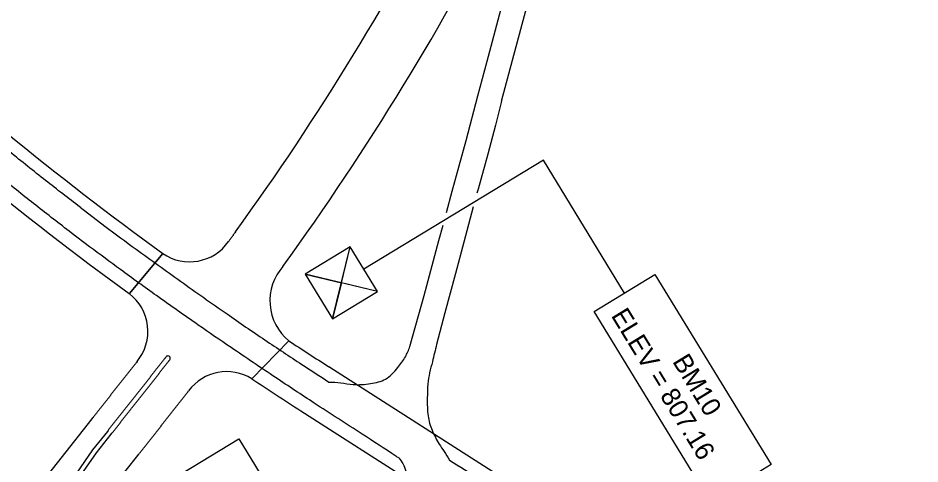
# Model space of a CAD drawing. Extents: x 1771071 to 1790027, y 804210 to 823391.
# Drawn here: x 1782402 to 1783163, y 814217 to 814593 of the extents above; entities that cross this region are included whole.
import ezdxf

# ---------------------------------------------------------------- set-up
doc = ezdxf.new("R2010")
doc.units = 0
for name, color, linetype in [('Default', 7, 'Continuous'), ('Exist Roads EOP', 7, 'Continuous'), ('Old_Level_57', 7, 'Continuous'), ('Prop Dimension Text', 7, 'Continuous'), ('Proposed Right of Way Monument PSD Text', 7, 'Continuous'), ('Scratch_Level_1', 7, 'Continuous'), ('Scratch_Level_8', 7, 'Continuous')]:
    doc.layers.add(name, color=color, linetype=linetype)

msp = doc.modelspace()

# ---------------------------------------------------------------- linework, layer by layer
at = {"layer": 'Default'}
msp.add_lwpolyline([(1782914.26, 814360.69), (1782845.7, 814472.9), (1782694.13, 814380.96)], dxfattribs=at)
for points in [[(1782939.86, 814376.33), (1783037.78, 814216.07), (1782986.58, 814184.78), (1782888.66, 814345.05)], [(1782588.69, 814237.9), (1782699.11, 814057.19), (1782626.99, 814013.12), (1782516.58, 814193.83)]]:
    msp.add_lwpolyline(points, close=True, dxfattribs=at)
at = {"layer": 'Exist Roads EOP'}
for points in [[(1782810.5, 814522.45), (1782819.71, 814557.13), (1782833.63, 814609.67), (1782845.19, 814652.34), (1782853.11, 814682.7), (1782866.83, 814733.67), (1782880.33, 814784.04), (1782896.83, 814847.05), (1782904.69, 814876.34), (1782917.48, 814926.43), (1782930.77, 814976.43), (1782943.98, 815026.78), (1782949.05, 815045.92), (1782955.94, 815070.93), (1782968.77, 815118.62), (1782976.32, 815145.42), (1782981.66, 815163.9), (1782994.39, 815213.76), (1783001.18, 815239.78), (1783009.61, 815271.62)], [(1782798.27, 814556.34), (1782809.82, 814599.63), (1782821.24, 814641.98), (1782833.33, 814687.58), (1782844.77, 814730.36), (1782855.02, 814768.66), (1782860.01, 814788.32), (1782866.57, 814813.78), (1782876.56, 814850.36), (1782887.82, 814892.28), (1782899.33, 814935.44), (1782909.53, 814975.79), (1782921.25, 815019.23), (1782932.71, 815062.01), (1782944.15, 815104.21), (1782955.09, 815145.17), (1782966.82, 815189.08), (1782971.17, 815207.42), (1782981.42, 815245.29), (1782983.08, 815250.42)], [(1782763.97, 814428.7), (1782768.85, 814446.71), (1782780.46, 814489.35), (1782790.34, 814526.96), (1782798.27, 814556.34)], [(1782810.5, 814522.45), (1782805.42, 814502.23), (1782798.82, 814477.74), (1782790.59, 814448.3), (1782789.65, 814444.83)], [(1782786.58, 814433.49), (1782778.49, 814403.65), (1782771.5, 814377.24), (1782762.64, 814343.92), (1782755.65, 814317.36)], [(1782733.16, 814315.62), (1782745.18, 814358.58), (1782757.57, 814405.12), (1782761.06, 814418)]]:
    msp.add_lwpolyline(points, dxfattribs=at)
for points in [[(1782454.8, 814433.05), (1782425.79, 814455.52), (1782395.47, 814479.87), (1782368.44, 814502.06), (1782336.7, 814528.74), (1782306.5, 814555), (1782272.52, 814585.37), (1782237.96, 814617.26), (1782203.42, 814650.14), (1782169.77, 814683.38), (1782135.62, 814718.19), (1782114.92, 814739.97), (1782090.36, 814766.45), (1782056.11, 814804.23), (1782024.57, 814840.15), (1781996.1, 814874.23), (1781962.65, 814915.16), (1781930.52, 814956.23), (1781901.27, 814994.73), (1781879.88, 815023.5), (1781865.55, 815043.2)], [(1782447.39, 814411.49), (1782417.41, 814434.76), (1782388.46, 814457.81), (1782364.95, 814476.92), (1782332.84, 814503.63), (1782317.89, 814516.39), (1782288.73, 814541.74), (1782259.15, 814568.04), (1782231.71, 814593.59), (1782203.19, 814620.46), (1782173.93, 814648.95), (1782145.34, 814677.22), (1782115.25, 814707.98), (1782082.01, 814743.51), (1782053.72, 814774.62), (1782020.97, 814811.58), (1781993.17, 814843.95), (1781966.57, 814876.13), (1781940.26, 814908.56), (1781913.84, 814942.34), (1781892.83, 814970.15), (1781866.04, 815005.9), (1781848.36, 815030.23)], [(1781123.7, 814794.56), (1781151.95, 814749.7), (1781175.35, 814711.94), (1781204.02, 814667.22), (1781230.05, 814626.42), (1781255.51, 814585.11), (1781282.93, 814541.39), (1781309.04, 814500.81), (1781338.07, 814453.82), (1781362.44, 814415.66), (1781389.1, 814373.22), (1781417.2, 814328.4), (1781443.82, 814286), (1781469.22, 814245.27), (1781496.33, 814201.88), (1781523.28, 814159.28), (1781551.49, 814114.9), (1781575, 814076.8), (1781602.27, 814034.47), (1781628.68, 813992.42), (1781657.71, 813946.44), (1781682.97, 813906.24), (1781710.54, 813862.11), (1781734.73, 813823.58), (1781763.09, 813779.24), (1781788.41, 813738.38), (1781814.81, 813696.35), (1781842.37, 813653.36), (1781868.91, 813610.68), (1781895.83, 813568.71), (1781924.39, 813523.58), (1781950.61, 813481.8), (1781976.68, 813442.67), (1782004.37, 813401.37), (1782031.99, 813360.12), (1782060.77, 813317.53), (1782089.19, 813276.64), (1782119.2, 813233.31), (1782146.2, 813195.67), (1782175.13, 813155.14), (1782204.07, 813115.4), (1782233.24, 813075.72), (1782263.79, 813034.43), (1782294.03, 812994.29), (1782325.04, 812953.86), (1782354.41, 812916.21), (1782385, 812877.38), (1782417.21, 812837.26), (1782449.43, 812797.65), (1782479.54, 812761.76), (1782513.17, 812720.66), (1782543.05, 812684.98), (1782576.35, 812645.89), (1782608.48, 812608.74), (1782640.69, 812571.37), (1782677.39, 812530.96), (1782710.34, 812494.65), (1782741.2, 812460.83), (1782775.54, 812424.09), (1782810.15, 812387.02), (1782844.36, 812350.73), (1782880.69, 812313.19), (1782914.85, 812277.64), (1782949.87, 812242.16), (1782985.13, 812206.92), (1783022.44, 812170.42), (1783054.86, 812138.57), (1783094.75, 812100.54), (1783130.02, 812066.91), (1783162.74, 812036.24), (1783200.85, 812001.49), (1783239.6, 811965.96), (1783275.52, 811933.35), (1783312.46, 811900.79)], [(1782664.68, 814285.69), (1782674.84, 814285.07), (1782685.21, 814283.59), (1782699.97, 814284.44), (1782712.52, 814288.15), (1782722.95, 814298), (1782729.29, 814306.99), (1782733.16, 814315.62)], [(1782755.65, 814317.36), (1782752.06, 814302.79), (1782748.2, 814284.21), (1782747.8, 814272.16), (1782748.44, 814257.13), (1782751.78, 814245), (1782757.87, 814233.38), (1782761.88, 814227.14), (1782766.5, 814219.88)], [(1782723.67, 814221.68), (1782727.13, 814216.98), (1782729.81, 814210.47), (1782732.01, 814203.23), (1782733.27, 814197.25), (1782734.23, 814187.61)]]:
    msp.add_spline(points, degree=3, dxfattribs=at)
at = {"layer": 'Old_Level_57'}
for p, q in [((1782667.92, 814339.04), (1782682.6, 814399.83)), ((1782705.65, 814362.09), (1782644.86, 814376.77))]:
    msp.add_line(p, q, dxfattribs=at)
msp.add_lwpolyline([(1782682.6, 814399.83), (1782644.86, 814376.77), (1782667.92, 814339.04), (1782705.65, 814362.09)], close=True, dxfattribs=at)
for points in [[(1782675.26, 814369.43), (1782682.6, 814399.83), (1782644.86, 814376.77), (1782675.26, 814369.43)], [(1782675.26, 814369.43), (1782667.92, 814339.04), (1782705.65, 814362.09), (1782675.26, 814369.43)]]:
    msp.add_lwpolyline(points, dxfattribs=at)
at = {"layer": 'Prop Dimension Text'}
for p, q in [((1782530.59, 814306.82), (1782529.6, 814307.59)), ((1782477.83, 814244.1), (1782465.41, 814228.41)), ((1782468.56, 814225.95), (1782480.97, 814241.62)), ((1782465.41, 814228.41), (1782350.67, 814064.15)), ((1782353.82, 814061.69), (1782468.56, 814225.95))]:
    msp.add_line(p, q, dxfattribs=at)
msp.add_lwpolyline([(1782527.36, 814306.96), (1782527.36, 814306.96)], dxfattribs=at)
for start, end in [(70.46317, 141.44737), (321.44737, 33.62467)]:
    msp.add_arc((1782528.93, 814305.71), 2, start, end, dxfattribs=at)
for points in [[(1782527.36, 814306.96), (1782527.01, 814306.51), (1782526.66, 814306.06), (1782526.31, 814305.61), (1782525.76, 814304.91), (1782525.21, 814304.2), (1782524.65, 814303.49), (1782524.1, 814302.78), (1782523.54, 814302.07), (1782522.99, 814301.36), (1782522.44, 814300.65), (1782521.88, 814299.94), (1782521.33, 814299.24), (1782520.77, 814298.53), (1782520.22, 814297.82), (1782519.66, 814297.11), (1782519.11, 814296.4), (1782518.55, 814295.69), (1782518, 814294.99), (1782517.44, 814294.28), (1782516.88, 814293.57), (1782516.33, 814292.86), (1782515.77, 814292.15), (1782515.22, 814291.45), (1782514.66, 814290.74), (1782514.11, 814290.03), (1782513.55, 814289.32), (1782512.99, 814288.62), (1782512.44, 814287.91), (1782511.88, 814287.2), (1782511.32, 814286.49), (1782510.77, 814285.79), (1782510.21, 814285.08), (1782509.65, 814284.37), (1782509.1, 814283.66), (1782508.54, 814282.96), (1782507.98, 814282.25), (1782507.43, 814281.54), (1782506.87, 814280.84), (1782506.31, 814280.13), (1782505.76, 814279.42), (1782505.2, 814278.71), (1782504.64, 814278.01), (1782504.08, 814277.3), (1782503.53, 814276.59), (1782502.97, 814275.89), (1782502.41, 814275.18), (1782501.85, 814274.47), (1782501.3, 814273.77), (1782500.74, 814273.06), (1782500.18, 814272.35), (1782499.62, 814271.65), (1782499.06, 814270.94), (1782498.51, 814270.23), (1782497.95, 814269.53), (1782497.39, 814268.82), (1782496.83, 814268.11), (1782496.27, 814267.41), (1782495.71, 814266.7), (1782495.16, 814265.99), (1782494.6, 814265.29), (1782494.04, 814264.58), (1782493.48, 814263.88), (1782492.92, 814263.17), (1782492.36, 814262.46), (1782491.81, 814261.76), (1782491.25, 814261.05), (1782490.69, 814260.34), (1782490.13, 814259.64), (1782489.57, 814258.93), (1782489.01, 814258.22), (1782488.45, 814257.52), (1782487.89, 814256.81), (1782487.34, 814256.11), (1782486.78, 814255.4), (1782486.22, 814254.69), (1782485.66, 814253.99), (1782485.1, 814253.28), (1782484.54, 814252.57), (1782483.98, 814251.87), (1782483.42, 814251.16), (1782482.86, 814250.46), (1782482.3, 814249.75), (1782481.75, 814249.04), (1782481.19, 814248.34), (1782480.63, 814247.63), (1782480.07, 814246.92), (1782479.51, 814246.22), (1782478.95, 814245.51), (1782478.39, 814244.81), (1782477.83, 814244.1)], [(1782480.97, 814241.62), (1782481.53, 814242.32), (1782482.09, 814243.03), (1782482.64, 814243.73), (1782483.2, 814244.44), (1782483.76, 814245.15), (1782484.32, 814245.85), (1782484.88, 814246.56), (1782485.44, 814247.27), (1782486, 814247.97), (1782486.56, 814248.68), (1782487.12, 814249.39), (1782487.68, 814250.09), (1782488.24, 814250.8), (1782488.8, 814251.5), (1782489.35, 814252.21), (1782489.91, 814252.92), (1782490.47, 814253.62), (1782491.03, 814254.33), (1782491.59, 814255.04), (1782492.15, 814255.74), (1782492.71, 814256.45), (1782493.27, 814257.16), (1782493.83, 814257.86), (1782494.38, 814258.57), (1782494.94, 814259.27), (1782495.5, 814259.98), (1782496.06, 814260.69), (1782496.62, 814261.39), (1782497.18, 814262.1), (1782497.74, 814262.81), (1782498.29, 814263.51), (1782498.85, 814264.22), (1782499.41, 814264.93), (1782499.97, 814265.63), (1782500.53, 814266.34), (1782501.09, 814267.05), (1782501.64, 814267.75), (1782502.2, 814268.46), (1782502.76, 814269.17), (1782503.32, 814269.88), (1782503.88, 814270.58), (1782504.44, 814271.29), (1782504.99, 814272), (1782505.55, 814272.7), (1782506.11, 814273.41), (1782506.67, 814274.12), (1782507.22, 814274.82), (1782507.78, 814275.53), (1782508.34, 814276.24), (1782508.9, 814276.95), (1782509.45, 814277.65), (1782510.01, 814278.36), (1782510.57, 814279.07), (1782511.13, 814279.78), (1782511.68, 814280.48), (1782512.24, 814281.19), (1782512.8, 814281.9), (1782513.35, 814282.61), (1782513.91, 814283.31), (1782514.47, 814284.02), (1782515.02, 814284.73), (1782515.58, 814285.44), (1782516.14, 814286.14), (1782516.69, 814286.85), (1782517.25, 814287.56), (1782517.81, 814288.27), (1782518.36, 814288.98), (1782518.92, 814289.68), (1782519.48, 814290.39), (1782520.03, 814291.1), (1782520.59, 814291.81), (1782521.14, 814292.52), (1782521.7, 814293.23), (1782522.25, 814293.94), (1782522.81, 814294.64), (1782523.36, 814295.35), (1782523.92, 814296.06), (1782524.48, 814296.77), (1782525.03, 814297.48), (1782525.59, 814298.19), (1782526.14, 814298.9), (1782526.69, 814299.61), (1782527.25, 814300.32), (1782527.8, 814301.02), (1782528.36, 814301.73), (1782528.91, 814302.44), (1782529.47, 814303.15), (1782529.81, 814303.59), (1782530.15, 814304.03), (1782530.49, 814304.46)]]:
    msp.add_open_spline(points, degree=3, dxfattribs=at)
at = {"layer": 'Scratch_Level_1'}
for p, q in [((1782454.8, 814433.05), (1782475.72, 814417.11)), ((1782462.86, 814399.8), (1782447.39, 814411.49))]:
    msp.add_line(p, q, dxfattribs=at)
for points in [[(1782475.72, 814417.11), (1782502.13, 814397.66), (1782539.56, 814370.71), (1782578.8, 814343.11), (1782610.76, 814321.2), (1782641.94, 814300.58), (1782664.68, 814285.69)], [(1782723.67, 814221.68), (1782721.33, 814223.19), (1782692.8, 814241.75), (1782652.47, 814267.87), (1782619.8, 814289.45), (1782582.18, 814314.76), (1782554.6, 814333.65), (1782519.33, 814358.55), (1782488.95, 814380.46), (1782462.86, 814399.8)], [(1782766.5, 814219.88), (1782791.69, 814203.81), (1782832.73, 814177.58)]]:
    msp.add_spline(points, degree=3, dxfattribs=at)
at = {"layer": 'Scratch_Level_8'}
for p, q in [((1782496.39, 814360.22), (1782524.58, 814394.12)), ((1782496.39, 814360.22), (1782524.58, 814394.12)), ((1782524.58, 814394.12), (1782496.39, 814360.22)), ((1782630.97, 814320.49), (1782599.81, 814288.35)), ((1782630.97, 814320.49), (1782599.81, 814288.35)), ((1782599.81, 814288.35), (1782630.97, 814320.49)), ((1783161.34, 813981.02), (1782664.74, 814298.57)), ((1782641.03, 814261.5), (1783137.64, 813943.95)), ((1782464.72, 814254.56), (1781921.58, 813568.53)), ((1782274, 813933.92), (1782503.53, 814223.83))]:
    msp.add_line(p, q, dxfattribs=at)
for centre, radius, start, end in [((1784215.15, 816723.25), 2878, 220.79704, 234.02645), ((1784215.15, 816723.25), 2922, 220.79704, 233.96949), ((1780718.84, 815764.32), 2305.25, 324.09033, 332.9908), ((1780718.84, 815764.32), 2354.75, 324.08963, 332.9908), ((1782547.27, 814427.08), 40.01, 235.46267, 325.28496), ((1782658.46, 814354.21), 43.51, 138.18524, 230.81193), ((1782472.08, 814328.44), 40.01, 320.48337, 52.58911), ((1784215.15, 816723.25), 2878, 236.60245, 237.40395), ((1782578.6, 814254.42), 40.01, 57.98892, 143.47609), ((1784215.15, 816723.25), 2922, 236.43927, 237.40395)]:
    msp.add_arc(centre, radius, start, end, dxfattribs=at)
for points in [[(1782585.96, 814412.27), (1782585.44, 814411.55), (1782584.91, 814410.82), (1782584.38, 814410.1), (1782583.86, 814409.38), (1782583.34, 814408.65), (1782582.81, 814407.93), (1782582.29, 814407.21), (1782581.76, 814406.49), (1782581.24, 814405.77), (1782580.88, 814405.28), (1782580.52, 814404.79), (1782580.16, 814404.29)], [(1782502.94, 814302.98), (1782502.47, 814302.37), (1782501.99, 814301.76), (1782501.51, 814301.15), (1782500.95, 814300.44), (1782500.4, 814299.74), (1782499.84, 814299.03), (1782499.29, 814298.32), (1782498.73, 814297.62), (1782498.18, 814296.91), (1782497.62, 814296.2), (1782497.07, 814295.5), (1782496.51, 814294.79), (1782495.95, 814294.09), (1782495.4, 814293.38), (1782494.84, 814292.67), (1782494.29, 814291.97), (1782493.73, 814291.26), (1782493.17, 814290.56), (1782492.62, 814289.85), (1782492.06, 814289.15), (1782491.5, 814288.44), (1782490.95, 814287.73), (1782490.39, 814287.03), (1782489.83, 814286.32), (1782489.28, 814285.62), (1782488.72, 814284.91), (1782488.16, 814284.2), (1782487.61, 814283.5), (1782487.05, 814282.79), (1782486.49, 814282.09), (1782485.94, 814281.38), (1782485.38, 814280.68), (1782484.82, 814279.97), (1782484.26, 814279.26), (1782483.71, 814278.56), (1782483.15, 814277.85), (1782482.59, 814277.15), (1782482.03, 814276.44), (1782481.47, 814275.74), (1782480.92, 814275.03), (1782480.36, 814274.32), (1782479.8, 814273.62), (1782479.24, 814272.91), (1782478.68, 814272.21), (1782478.13, 814271.5), (1782477.57, 814270.8), (1782477.01, 814270.09), (1782476.45, 814269.38), (1782475.89, 814268.68), (1782475.33, 814267.97), (1782474.78, 814267.27), (1782474.22, 814266.56), (1782473.66, 814265.85), (1782473.1, 814265.15), (1782472.54, 814264.44), (1782471.98, 814263.74), (1782471.42, 814263.03), (1782470.87, 814262.32), (1782470.31, 814261.62), (1782469.75, 814260.91), (1782469.19, 814260.21), (1782468.63, 814259.5), (1782468.07, 814258.79), (1782467.51, 814258.09), (1782466.95, 814257.38), (1782466.39, 814256.68), (1782465.83, 814255.97), (1782465.27, 814255.26), (1782464.72, 814254.56)], [(1782503.53, 814223.83), (1782504.08, 814224.54), (1782504.64, 814225.24), (1782505.2, 814225.95), (1782505.76, 814226.66), (1782506.32, 814227.36), (1782506.88, 814228.07), (1782507.44, 814228.78), (1782508, 814229.48), (1782508.56, 814230.19), (1782509.12, 814230.9), (1782509.68, 814231.6), (1782510.24, 814232.31), (1782510.8, 814233.02), (1782511.36, 814233.72), (1782511.92, 814234.43), (1782512.48, 814235.14), (1782513.03, 814235.84), (1782513.59, 814236.55), (1782514.15, 814237.26), (1782514.71, 814237.97), (1782515.27, 814238.67), (1782515.83, 814239.38), (1782516.39, 814240.09), (1782516.95, 814240.79), (1782517.51, 814241.5), (1782518.07, 814242.21), (1782518.63, 814242.92), (1782519.19, 814243.63), (1782519.75, 814244.33), (1782520.31, 814245.04), (1782520.87, 814245.75), (1782521.43, 814246.46), (1782521.99, 814247.16), (1782522.55, 814247.87), (1782523.11, 814248.58), (1782523.66, 814249.29), (1782524.22, 814250), (1782524.78, 814250.7), (1782525.34, 814251.41), (1782525.9, 814252.12), (1782526.46, 814252.83), (1782527.02, 814253.54), (1782527.58, 814254.25), (1782528.14, 814254.96), (1782528.7, 814255.66), (1782529.26, 814256.37), (1782529.82, 814257.08), (1782530.38, 814257.79), (1782530.93, 814258.5), (1782531.49, 814259.21), (1782532.05, 814259.92), (1782532.61, 814260.63), (1782533.17, 814261.34), (1782533.73, 814262.05), (1782534.29, 814262.76), (1782534.85, 814263.47), (1782535.41, 814264.18), (1782535.96, 814264.89), (1782536.52, 814265.6), (1782537.08, 814266.31), (1782537.64, 814267.02), (1782538.2, 814267.73), (1782538.76, 814268.44), (1782539.32, 814269.15), (1782539.87, 814269.86), (1782540.43, 814270.57), (1782540.99, 814271.28), (1782541.55, 814271.99), (1782542.11, 814272.7), (1782542.67, 814273.41), (1782543.22, 814274.12), (1782543.78, 814274.84), (1782544.34, 814275.55), (1782544.9, 814276.26), (1782545.45, 814276.97), (1782545.78, 814277.39), (1782546.11, 814277.81), (1782546.44, 814278.23)]]:
    msp.add_open_spline(points, degree=3, dxfattribs=at)

# ---------------------------------------------------------------- texts
at = {"layer": 'Proposed Right of Way Monument PSD Text'}
for s, p in [('ELEV = 807.16', (1782902.41, 814341.73)), ('BM10', (1782954.15, 814303.07))]:
    msp.add_text(s, height=16, rotation=301.42495, dxfattribs=at).set_placement(p)

doc.saveas('drawing.dxf')
